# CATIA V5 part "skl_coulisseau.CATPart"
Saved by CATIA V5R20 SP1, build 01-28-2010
Part number: skl_coulisseau
Publications: "Plan_ref", "Point_projete", "Point_ref", "Point_a2", "Plan_pivot_avec_bielle3", "segment_Pt_ref_Pt_a2", "axe_ref", "axe_pivot", "Pt_milieu_coulisseau", "Plan_construction_coulisseau"
Bounding box of the stored display mesh (mm): x 0 to 40, y 0 to 400, z 0 to 0
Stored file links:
  C:\Users\Fabien-port\Desktop\test\skl_coulisseau.CATPart
  C:\Users\Fabien-port\Desktop\test\ass_skl_mecanisme_a_coulisseau.CATProduct
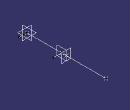
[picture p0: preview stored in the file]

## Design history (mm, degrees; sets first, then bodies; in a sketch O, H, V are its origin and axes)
Set1
  Plane1 "Plan_ref": linked copy from another document
  Point1 "Point_projete": linked copy from another document
  Point2 "Point_ref": linked copy from another document
  Point3 "Point_a2": linked copy from another document
  Line1 "axe_ref": linked copy from another document
  Plane2 "Plan_ortho_ref": linked copy from another document
Set2
  Plane3 "Plan_pivot_avec_bielle3": type OffsetPt, RefPlane Plane1, RefPoint Point1
  Line2 "segment_Pt_ref_Pt_a2": type PtPt, FirstPoint Point2, SecondPoint Point3
  Line3 "axe_pivot": type PtDir, RefPoint Point1, Direction Line1, Start 0, End 40
  Point4 "Pt_milieu_coulisseau": type Between, FirstPoint Point2, SecondPoint Point3, Ratio 0.5
  Plane4 "Plan_construction_coulisseau": type OffsetPt, RefPlane Plane2, RefPoint Point4
Body1 (main body)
